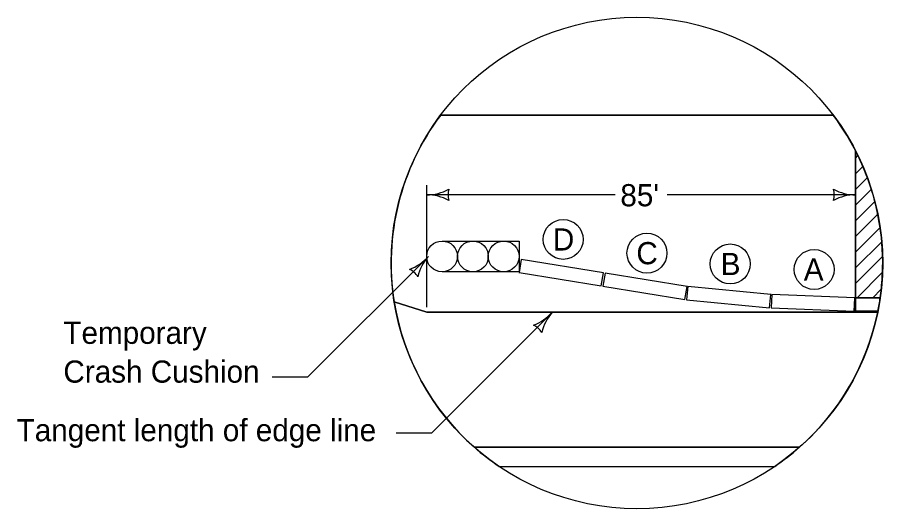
# Model space of a CAD drawing. Extents: x 10133 to 2270741, y 5363 to 1733450.
# Drawn here: x 24586 to 25366, y 6058 to 6501 of the extents above; entities that cross this region are included whole.
import ezdxf

# ---------------------------------------------------------------- set-up
doc = ezdxf.new("R2010")
doc.units = 0
for name, color, linetype in [('dsnNonPlotable', 7, 'Continuous'), ('dsnShtPlotShapeBatchPrint', 7, 'Continuous'), ('dsnStdBlockModified', 7, 'Continuous'), ('dsnStdBorder', 7, 'Continuous'), ('dsnStdLabel', 7, 'Continuous'), ('Level 12', 7, 'Continuous'), ('Level 2', 7, 'Continuous')]:
    doc.layers.add(name, color=color, linetype=linetype)

msp = doc.modelspace()

# ---------------------------------------------------------------- linework, layer by layer
at = {"layer": 'dsnNonPlotable'}
for p, q in [((24967.58, 6412.65), (25321.41, 6412.65)), ((25341.67, 6247.85), (25341.67, 6380.34)), ((25341.67, 6373.87), (25343.82, 6376.03)), ((25341.67, 6359.73), (25348.25, 6366.31)), ((25341.67, 6345.59), (25352.28, 6356.2)), ((25341.67, 6331.45), (25355.89, 6345.67)), ((25341.67, 6317.3), (25359.04, 6334.67)), ((25341.67, 6303.16), (25361.68, 6323.17)), ((25341.67, 6289.02), (25363.78, 6311.13)), ((25341.67, 6274.88), (25365.25, 6298.46)), ((25341.67, 6260.73), (25366.01, 6285.07)), ((25342.93, 6247.85), (25365.93, 6270.85)), ((25357.07, 6247.85), (25364.82, 6255.6)), ((24925.68, 6244.31), (24954.97, 6234.85)), ((24954.97, 6234.85), (25361.6, 6234.85)), ((24997.93, 6113.03), (25291.06, 6113.03))]:
    msp.add_line(p, q, dxfattribs=at)
for points in [[(25114.25, 6270.38), (25040.24, 6282.52), (25038.29, 6270.67), (25112.31, 6258.54)], [(25189.74, 6258.01), (25115.73, 6270.14), (25113.79, 6258.3), (25187.8, 6246.17)], [(25265.15, 6250.78), (25190.49, 6257.88), (25189.35, 6245.94), (25264.01, 6238.83)], [(25340.93, 6247.85), (25265.99, 6250.84), (25265.51, 6238.85), (25340.45, 6235.85)]]:
    msp.add_lwpolyline(points, close=True, dxfattribs=at)
msp.add_lwpolyline([(25361.8, 6235.85), (25341.67, 6235.85), (25341.67, 6247.85), (25363.85, 6247.85)], dxfattribs=at)
at = {"layer": 'dsnShtPlotShapeBatchPrint'}
for centre in [(25078.04, 6300.47), (25153.54, 6288.1), (25228.62, 6278.36), (25304.26, 6273.37)]:
    msp.add_circle(centre, 18, dxfattribs=at)
at = {"layer": 'dsnStdBlockModified'}
for p, q in [((24968.85, 6299.04), (25038.29, 6299.04)), ((25038.29, 6299.04), (25038.29, 6271.26)), ((25038.29, 6271.26), (24968.85, 6271.26)), ((25037.69, 6269.98), (25037.69, 6269.98))]:
    msp.add_line(p, q, dxfattribs=at)
for centre in [(24968.85, 6285.15), (24968.85, 6285.15), (24996.63, 6285.15), (24996.63, 6285.15), (25024.41, 6285.15), (25024.41, 6285.15)]:
    msp.add_circle(centre, 13.89, dxfattribs=at)
at = {"layer": 'dsnStdBorder'}
for centre, radius in [((25144.5, 6279.22), 221.59), ((24968.85, 6285.15), 13.89), ((24996.63, 6285.15), 13.89), ((25024.41, 6285.15), 13.89)]:
    msp.add_circle(centre, radius, dxfattribs=at)
at = {"layer": 'dsnStdLabel'}
msp.add_line((25341.67, 6252.4), (25341.67, 6349.4), dxfattribs=at)
at = {"layer": 'Level 12'}
for p, q in [((24954.97, 6239.4), (24954.97, 6349.4)), ((25341.67, 6252.4), (25341.67, 6349.4)), ((25124.97, 6340.71), (24954.97, 6340.71)), ((25341.67, 6340.71), (25171.67, 6340.71)), ((24956.59, 6285.11), (24847.76, 6176.52)), ((25068.3, 6234.79), (24959.46, 6126.2)), ((24815.76, 6176.52), (24847.76, 6176.52)), ((24927.46, 6126.2), (24959.46, 6126.2))]:
    msp.add_line(p, q, dxfattribs=at)
for centre, radius, start, end in [((24954.97, 6383.21), 42.5, 270, 298.07249), ((24990.6, 6340.71), 16.42, 162.26665, 197.73335), ((25306.03, 6340.71), 16.42, 342.26665, 17.73335), ((25341.67, 6383.21), 42.5, 241.92751, 270), ((24954.97, 6298.21), 42.5, 61.92751, 90), ((25341.67, 6298.21), 42.5, 90, 118.07249), ((24924.62, 6313.31), 42.5, 290.47233, 318.54482), ((24988.32, 6257.04), 42.5, 138.54482, 166.61731), ((24932.88, 6258.47), 16.42, 30.81146, 66.27817), ((25036.32, 6262.99), 42.5, 290.47233, 318.54482), ((25100.03, 6206.72), 42.5, 138.54482, 166.61731), ((25044.58, 6208.15), 16.42, 30.81146, 66.27817)]:
    msp.add_arc(centre, radius, start, end, dxfattribs=at)
at = {"layer": 'Level 2'}
for p, q in [((25321.41, 6412.65), (24967.58, 6412.65)), ((24925.68, 6244.31), (24954.97, 6234.85)), ((24954.97, 6234.85), (24925.68, 6244.31)), ((25341.67, 6247.85), (25363.85, 6247.85)), ((24954.97, 6234.85), (25361.6, 6234.85)), ((25361.6, 6234.85), (24954.97, 6234.85)), ((24997.93, 6113.03), (25291.06, 6113.03)), ((25291.06, 6113.03), (24997.93, 6113.03)), ((25020.23, 6095.76), (25268.76, 6095.76))]:
    msp.add_line(p, q, dxfattribs=at)
for points in [[(25341.67, 6380.34), (25341.67, 6340.71), (25341.67, 6247.85)], [(25114.25, 6270.38), (25040.24, 6282.52), (25038.29, 6270.67), (25112.31, 6258.54), (25114.25, 6270.38)], [(25189.74, 6258.01), (25115.73, 6270.14), (25113.79, 6258.3), (25187.8, 6246.17), (25189.74, 6258.01)], [(25265.15, 6250.78), (25190.49, 6257.88), (25189.35, 6245.94), (25264.01, 6238.83), (25265.15, 6250.78)], [(25340.93, 6247.85), (25265.99, 6250.84), (25265.51, 6238.85), (25340.45, 6235.85), (25340.93, 6247.85)], [(25363.85, 6247.85), (25341.67, 6247.85), (25341.67, 6235.85), (25361.8, 6235.85)], [(25361.8, 6235.85), (25341.67, 6235.85), (25341.67, 6247.85), (25363.85, 6247.85)]]:
    msp.add_lwpolyline(points, dxfattribs=at)
for start, end in [(142.97733, 189.06592), (351.86215, 37.02267), (351.86215, 27.15053), (189.06592, 228.59062), (348.71381, 351.86215), (311.40938, 348.45002), (348.45002, 348.71381), (228.59062, 235.88896), (304.11104, 311.40938)]:
    msp.add_arc((25144.5, 6279.22), 221.59, start, end, dxfattribs=at)

# ---------------------------------------------------------------- texts
at = {"layer": 'dsnShtPlotShapeBatchPrint'}
for s, p in [('D', (25068.7, 6290.47)), ('C', (25144, 6278.1)), ('B', (25220.05, 6268.36)), ('A', (25294.92, 6263.37))]:
    msp.add_text(s, height=20, dxfattribs=at).set_placement(p)
at = {"layer": 'Level 12'}
for s, p in [("85'", (25129.56, 6330.35)), ('Temporary ', (24627.41, 6206.29)), ('Crash Cushion', (24627.41, 6171.29)), ('Tangent length of edge line', (24585.27, 6118.48))]:
    msp.add_text(s, height=20, dxfattribs=at).set_placement(p)

doc.saveas('drawing.dxf')
